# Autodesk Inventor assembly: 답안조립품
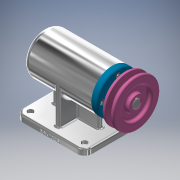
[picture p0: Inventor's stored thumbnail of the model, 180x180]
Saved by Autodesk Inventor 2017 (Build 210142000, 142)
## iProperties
Part Number: 답안조립품
Material: 일반
Document SubType Name: Assembly
Designer: 00-00
Author: 00-00
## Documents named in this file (12)
- C:\Users\00-00\Desktop\701004V1013\답안조립품.iam
- C:\Users\00-00\Desktop\701004V1013\본체.ipt
- C:\Users\00-00\Desktop\701004V1013\V벨트풀리.ipt
- C:\Users\00-00\Desktop\701004V1013\멈춤나사 M3.ipt
- C:\Users\00-00\Desktop\701004V1013\베어링 6004.ipt
- C:\Users\00-00\Desktop\701004V1013\베어링 51202.ipt
- C:\Users\00-00\Desktop\701004V1013\볼트 M4.ipt
- C:\Users\00-00\Desktop\701004V1013\어댑터슬리브.ipt
- C:\Users\00-00\Desktop\701004V1013\오일 실.ipt
- C:\Users\00-00\Desktop\701004V1013\축.ipt
- C:\Users\00-00\Desktop\701004V1013\커버.ipt
- C:\Users\00-00\Desktop\701004V1013\키 5 x 5 x 16.ipt
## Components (1 placed, 1 different names)
1. V벨트풀리:1 — 각도:1
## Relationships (1: Angle 1)
- 각도:1 [Angle]: V벨트풀리:1
